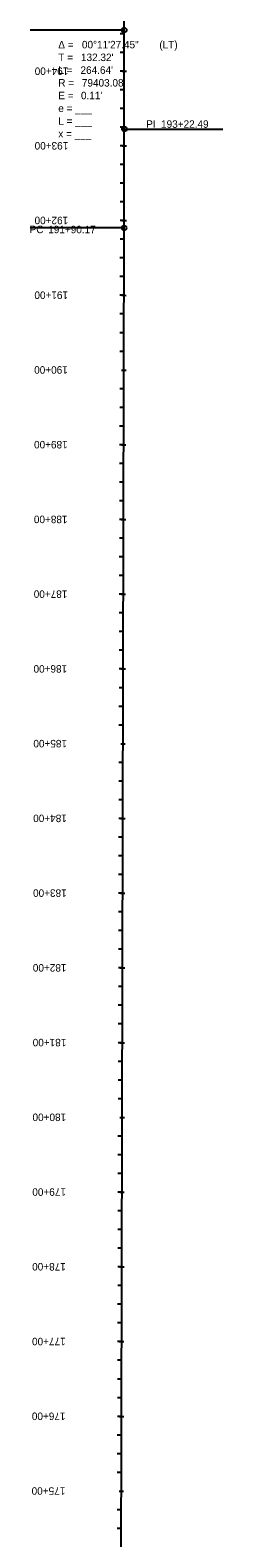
# Model space of a CAD drawing. Extents: x 23417911 to 23421158, y 6737892 to 6791804.
# Drawn here: x 23418172 to 23418431, y 6743912 to 6745930 of the extents above; entities that cross this region are included whole.
import ezdxf

# ---------------------------------------------------------------- set-up
doc = ezdxf.new("R2010")
doc.units = 0
for name, color, linetype in [('Alignment', 7, 'Continuous'), ('TextAlignment', 7, 'Continuous'), ('TextAlignmentLrg', 7, 'Continuous'), ('TextAlignmentSml', 7, 'Continuous')]:
    doc.layers.add(name, color=color, linetype=linetype)

msp = doc.modelspace()

# ---------------------------------------------------------------- linework, layer by layer
at = {"layer": 'Alignment'}
for p, q in [((23418298.6, 6745929.6), (23418296.3, 6748119.1)), ((23418293.5, 6743464.3), (23418298.5, 6745664.9)), ((23418293.5, 6743464.3), (23418298.5, 6745664.9))]:
    msp.add_line(p, q, dxfattribs=at)
msp.add_arc((23338895.6, 6745845.5), 79403.1, 359.869694, 0.060653, dxfattribs=at)
msp.add_arc((23338895.6, 6745845.5), 79403.1, 359.869694, 0.060653, dxfattribs=at)
at = {"layer": 'TextAlignment'}
for p, q in [((23418298.6, 6745929.6), (23418172.6, 6745929.4)), ((23418172.6, 6745929.4), (23418172.6, 6745929.4)), ((23418298.8, 6745797.2), (23418430.8, 6745797.2)), ((23418430.8, 6745797.2), (23418430.8, 6745797.2)), ((23418298.5, 6745664.9), (23418172.5, 6745665.2)), ((23418172.5, 6745665.2), (23418172.5, 6745665.2))]:
    msp.add_line(p, q, dxfattribs=at)
for centre in [(23418298.6, 6745929.6), (23418298.8, 6745797.2), (23418298.5, 6745664.9)]:
    msp.add_circle(centre, 3.12, dxfattribs=at)
at = {"layer": 'TextAlignmentLrg'}
for p, q in [((23418298.7, 6745874.8), (23418293.2, 6745874.8)), ((23418298.6, 6745774.8), (23418293.2, 6745774.8)), ((23418298.5, 6745674.8), (23418293, 6745674.8)), ((23418298.3, 6745574.8), (23418292.8, 6745574.8)), ((23418295, 6745474.8), (23418301.1, 6745474.7)), ((23418297.8, 6745374.8), (23418292.3, 6745374.8)), ((23418297.6, 6745274.8), (23418292.1, 6745274.8)), ((23418297.3, 6745174.8), (23418291.9, 6745174.8)), ((23418297.1, 6745074.8), (23418291.7, 6745074.8)), ((23418293.8, 6744974.8), (23418300, 6744974.8)), ((23418296.7, 6744874.8), (23418291.2, 6744874.8)), ((23418296.4, 6744774.8), (23418291, 6744774.8)), ((23418296.2, 6744674.8), (23418290.8, 6744674.8)), ((23418296, 6744574.8), (23418290.5, 6744574.8)), ((23418292.7, 6744474.8), (23418298.8, 6744474.8)), ((23418295.5, 6744374.8), (23418290.1, 6744374.8)), ((23418295.3, 6744274.8), (23418289.8, 6744274.8)), ((23418295.1, 6744174.8), (23418289.6, 6744174.8)), ((23418294.8, 6744074.8), (23418289.4, 6744074.8)), ((23418291.6, 6743974.8), (23418297.7, 6743974.8))]:
    msp.add_line(p, q, dxfattribs=at)
at = {"layer": 'TextAlignmentSml'}
for p, q in [((23418298.6, 6745924.8), (23418293.2, 6745924.8)), ((23418298.6, 6745899.8), (23418293.2, 6745899.8)), ((23418295.6, 6745874.8), (23418301.7, 6745874.8)), ((23418298.7, 6745849.8), (23418293.2, 6745849.8)), ((23418298.7, 6745824.8), (23418293.2, 6745824.8)), ((23418298.7, 6745799.8), (23418293.2, 6745799.8)), ((23418295.6, 6745774.8), (23418301.7, 6745774.8)), ((23418298.6, 6745749.8), (23418293.2, 6745749.8)), ((23418298.6, 6745724.8), (23418293.1, 6745724.8)), ((23418298.5, 6745699.8), (23418293.1, 6745699.8)), ((23418295.4, 6745674.8), (23418301.5, 6745674.7)), ((23418298.4, 6745649.8), (23418293, 6745649.8)), ((23418298.4, 6745624.8), (23418292.9, 6745624.8)), ((23418298.3, 6745599.8), (23418292.9, 6745599.8)), ((23418295.2, 6745574.8), (23418301.3, 6745574.7)), ((23418298.2, 6745549.8), (23418292.7, 6745549.8)), ((23418298.1, 6745524.8), (23418292.7, 6745524.8)), ((23418298.1, 6745499.8), (23418292.6, 6745499.8)), ((23418295, 6745474.8), (23418301.1, 6745474.7)), ((23418298, 6745449.8), (23418292.5, 6745449.8)), ((23418297.9, 6745424.8), (23418292.5, 6745424.8)), ((23418297.9, 6745399.8), (23418292.4, 6745399.8)), ((23418294.7, 6745374.8), (23418300.9, 6745374.7)), ((23418297.7, 6745349.8), (23418292.3, 6745349.8)), ((23418297.7, 6745324.8), (23418292.2, 6745324.8)), ((23418297.6, 6745299.8), (23418292.2, 6745299.8)), ((23418294.5, 6745274.8), (23418300.6, 6745274.8)), ((23418297.5, 6745249.8), (23418292.1, 6745249.8)), ((23418297.5, 6745224.8), (23418292, 6745224.8)), ((23418297.4, 6745199.8), (23418291.9, 6745199.8)), ((23418294.3, 6745174.8), (23418300.4, 6745174.8)), ((23418297.3, 6745149.8), (23418291.8, 6745149.8)), ((23418297.2, 6745124.8), (23418291.8, 6745124.8)), ((23418297.2, 6745099.8), (23418291.7, 6745099.8)), ((23418294.1, 6745074.8), (23418300.2, 6745074.8)), ((23418297.1, 6745049.8), (23418291.6, 6745049.8)), ((23418297, 6745024.8), (23418291.5, 6745024.8)), ((23418297, 6744999.8), (23418291.5, 6744999.8)), ((23418293.8, 6744974.8), (23418300, 6744974.8)), ((23418296.8, 6744949.8), (23418291.4, 6744949.8)), ((23418296.8, 6744924.8), (23418291.3, 6744924.8)), ((23418296.7, 6744899.8), (23418291.3, 6744899.8)), ((23418293.6, 6744874.8), (23418299.7, 6744874.8)), ((23418296.6, 6744849.8), (23418291.1, 6744849.8)), ((23418296.6, 6744824.8), (23418291.1, 6744824.8)), ((23418296.5, 6744799.8), (23418291, 6744799.8)), ((23418293.4, 6744774.8), (23418299.5, 6744774.8)), ((23418296.4, 6744749.8), (23418290.9, 6744749.8)), ((23418296.3, 6744724.8), (23418290.9, 6744724.8)), ((23418296.3, 6744699.8), (23418290.8, 6744699.8)), ((23418293.2, 6744674.8), (23418299.3, 6744674.8)), ((23418296.2, 6744649.8), (23418290.7, 6744649.8)), ((23418296.1, 6744624.8), (23418290.6, 6744624.8)), ((23418296, 6744599.8), (23418290.6, 6744599.8)), ((23418292.9, 6744574.8), (23418299, 6744574.8)), ((23418295.9, 6744549.8), (23418290.5, 6744549.8)), ((23418295.9, 6744524.8), (23418290.4, 6744524.8)), ((23418295.8, 6744499.8), (23418290.4, 6744499.8)), ((23418292.7, 6744474.8), (23418298.8, 6744474.8)), ((23418295.7, 6744449.8), (23418290.2, 6744449.8)), ((23418295.6, 6744424.8), (23418290.2, 6744424.8)), ((23418295.6, 6744399.8), (23418290.1, 6744399.8)), ((23418292.5, 6744374.8), (23418298.6, 6744374.8)), ((23418295.5, 6744349.8), (23418290, 6744349.8)), ((23418295.4, 6744324.8), (23418290, 6744324.8)), ((23418295.4, 6744299.8), (23418289.9, 6744299.8)), ((23418292.2, 6744274.8), (23418298.4, 6744274.8)), ((23418295.2, 6744249.8), (23418289.8, 6744249.8)), ((23418295.2, 6744224.8), (23418289.7, 6744224.8)), ((23418295.1, 6744199.8), (23418289.7, 6744199.8)), ((23418292, 6744174.8), (23418298.1, 6744174.8)), ((23418295, 6744149.8), (23418289.6, 6744149.8)), ((23418295, 6744124.8), (23418289.5, 6744124.8)), ((23418294.9, 6744099.8), (23418289.4, 6744099.8)), ((23418291.8, 6744074.8), (23418297.9, 6744074.8)), ((23418294.8, 6744049.8), (23418289.3, 6744049.8)), ((23418294.7, 6744024.8), (23418289.3, 6744024.8)), ((23418294.7, 6743999.8), (23418289.2, 6743999.8)), ((23418291.6, 6743974.8), (23418297.7, 6743974.8)), ((23418294.6, 6743949.8), (23418289.1, 6743949.8)), ((23418294.5, 6743924.8), (23418289, 6743924.8))]:
    msp.add_line(p, q, dxfattribs=at)

# ---------------------------------------------------------------- texts
at = {"layer": 'TextAlignment'}
for s, p in [('Δ = ', (23418210.2, 6745905.2)), ('00°11\'27.45"', (23418241.9, 6745905.2)), (' (LT)', (23418341.9, 6745905.2)), ('T = ', (23418210.2, 6745888.2)), ("132.32'", (23418240.6, 6745888.2)), ('L = ', (23418210.2, 6745871.1)), ("264.64'", (23418240, 6745871.1)), ('R = ', (23418210.2, 6745854.1)), ("79403.08'", (23418241.8, 6745854.1)), ('E = ', (23418210.2, 6745837.1)), ("0.11'", (23418240.6, 6745837.1)), ('e = ___ ', (23418210.2, 6745820)), ('L = ___', (23418210.2, 6745803)), ('x = ___', (23418210.2, 6745786))]:
    msp.add_text(s, height=10.02, dxfattribs=at).set_placement(p)
for s, rotation, p in [('PI ', 359.9652, (23418328, 6745798.9)), ('193+22.49', 359.9652, (23418347.9, 6745798.9)), ('PC', 359.8697, (23418171.8, 6745658)), ('191+90.17', 359.8697, (23418196.7, 6745657.9))]:
    msp.add_text(s, height=10.02, rotation=rotation, dxfattribs=at).set_placement(p)
at = {"layer": 'TextAlignmentLrg'}
for s, p in [('190+00', (23418223, 6745479.9)), ('185+00', (23418221.9, 6744979.9)), ('180+00', (23418220.8, 6744479.9)), ('175+00', (23418219.6, 6743979.9))]:
    msp.add_text(s, height=10.02, rotation=179.8697, dxfattribs=at).set_placement(p)
at = {"layer": 'TextAlignmentSml'}
for s, rotation, p in [('194+00', 180.0211, (23418223.7, 6745879.7)), ('193+00', 179.9489, (23418223.6, 6745779.8)), ('192+00', 179.8768, (23418223.5, 6745679.9)), ('191+00', 179.8697, (23418223.3, 6745579.9)), ('190+00', 179.8697, (23418223, 6745479.9)), ('189+00', 179.8697, (23418222.8, 6745379.9)), ('188+00', 179.8697, (23418222.6, 6745279.9)), ('187+00', 179.8697, (23418222.4, 6745179.9)), ('186+00', 179.8697, (23418222.1, 6745079.9)), ('185+00', 179.8697, (23418221.9, 6744979.9)), ('184+00', 179.8697, (23418221.7, 6744879.9)), ('183+00', 179.8697, (23418221.5, 6744779.9)), ('182+00', 179.8697, (23418221.2, 6744679.9)), ('181+00', 179.8697, (23418221, 6744579.9)), ('180+00', 179.8697, (23418220.8, 6744479.9)), ('179+00', 179.8697, (23418220.5, 6744379.9)), ('178+00', 179.8697, (23418220.3, 6744279.9)), ('177+00', 179.8697, (23418220.1, 6744179.9)), ('176+00', 179.8697, (23418219.9, 6744079.9)), ('175+00', 179.8697, (23418219.6, 6743979.9))]:
    msp.add_text(s, height=10.02, rotation=rotation, dxfattribs=at).set_placement(p)

doc.saveas('drawing.dxf')
